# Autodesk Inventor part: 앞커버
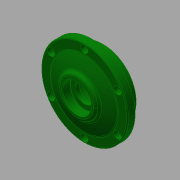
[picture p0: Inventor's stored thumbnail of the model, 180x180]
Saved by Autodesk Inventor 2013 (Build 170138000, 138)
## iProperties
Created: 2016-05
Part Number: 앞커버
Document SubType Name: Modeling
Designer: mduedu
Density: 2.71 g/cm^3
Material: 알루미늄 6061
Author: mduedu
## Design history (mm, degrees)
sketch "스케치1"
  geometry: C1 r 35 at (0, 0); C2 r 45 at (0, 0); 1 further point
  constraints: 2 centre point, 2 coincident
  dimensions: "d33" = 90 diameter of C2; "d34" = 70 diameter of C1
extrude "돌출1" new body sketch "스케치1" distance "d0" = 8; taper "d1" = 0 deg
extrude "돌출2" join sketch "스케치1" distance "d2" = 8; taper "d3" = 0 deg; dims "d35" = 12, "d36" = 0
sketch "스케치5"
  geometry: L1 (-45, 8)-(45, 8) reference; L2 (0, 0)-(0, 15); L3 (-45, 0)-(45, 0) reference; L4 (35, 8)-(0, 8); A1 r 91 centre (0, -76) between (35, 8) and (0, 15)
  constraints: 4 end point, 3 point on line, 2 point on circle, 1 centre point, 1 midpoint, 1 perpendicular
  dimensions: "d37" = 35 distance from line of L2 L4.start; "d39" = 7 distance from line of L1 L2.end
revolve "회전2" sketch "스케치5" stored, may be unused: angle "d40" = 90 deg
node "작업 평면1"
sketch "스케치6"
  geometry: C1 r 20 at (0, 0); 1 further point
  constraints: 1 centre point, 1 coincident
  dimensions: "d42" = 40 diameter of C1
extrude "돌출4" join sketch "스케치6" stored distance "d43" = 10; taper "d44" = 0 deg
sketch "스케치4"
  geometry: L1 (0, -12)-(0, 16); L2 (-20, -12)-(-20, 0); L3 (-20, 0)-(-15, 0); L4 (-15, 0)-(-15, 3); L5 (-15, 3)-(-10, 3); L6 (-10, 3)-(-10, 7.5); L7 (-10, 7.5)-(-15, 7.5); L8 (-15, 7.5)-(-15, 16); L9 (35, -12)-(-35, -12) reference; L10 (-20, 16)-(20, 16) reference; 1 further point
  constraints: 16 end point, 6 parallel, 3 point on line, 2 midpoint, 1 perpendicular, 1 vertical
  dimensions: "d15" = 40 diameter of L2 L1; "d16" = 30 diameter of L8 L1; "d18" = 12 distance of L2.start L2.end; "d19" = 3 distance of L3.end L4.end; "d20" = 30 diameter of L4 L1; "d21" = 20 diameter of L6 L1; "d45" = 8.5 distance of L7.end L8.end
revolve "회전1" sketch "스케치4" stored, may be unused: angle "d22" = 90 deg
fillet "모깎기2" dims "d23" = 3
fillet "모깎기3" dims "d24" = 0.3
chamfer "모따기2" distance "d46" = 1; stored, may be unused: second distance "d47" = 2, angle "d48" = 45 deg
fillet "모깎기4" dims "d49" = 3
fillet "모깎기5" dims "d50" = 3
fillet "모깎기6" dims "d51" = 1
sketch "스케치7" dims "d52" = 80
  geometry: C1 r 35.595 at (0, 0) reference; C2 r 44 at (0, 0) reference; 7 further points
  constraints: 2 vertical alignment, 1 coincident, 9 other
  dimensions: "d55" = 360 deg dimension on C1.centre point (0, 40) (derived)
sketch "스케치8"
  geometry: 6 further points
  constraints: 6 other
hole "구멍2" sketch "스케치8" at (-34.641, 20), (-34.641, -20), (0, -40), (34.641, -20), (34.641, 20), (0, 40) diameter "d57" = 4.5; stored, may be unused: countersink angle "d61" = 90 deg, drill point angle "d63" = 0 deg; dims "d58" = 6, "d59" = 8, "d60" = 4.6, "d62" = 8
chamfer "모따기3" distance "d64" = 0.8; stored, may be unused: second distance "d65" = 2, angle "d66" = 30 deg
node "솔리드1"
other parameters: "d41" = 8
